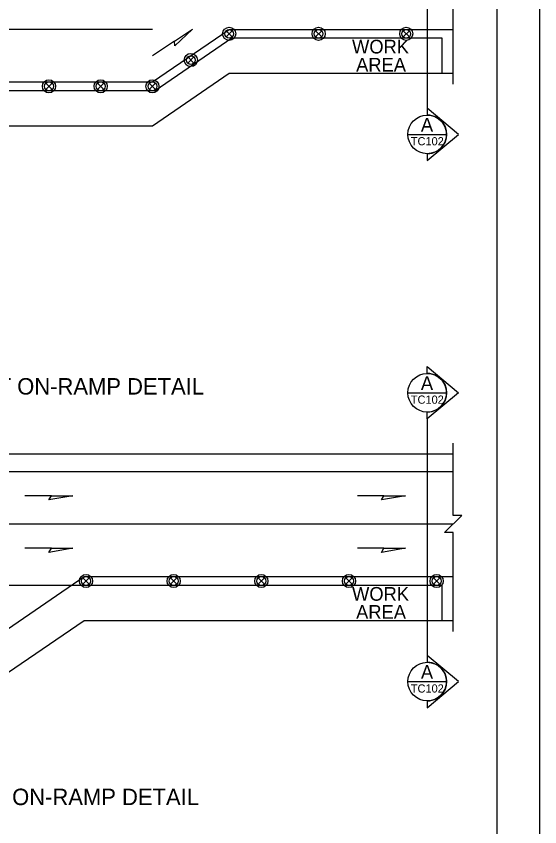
# Model space of a CAD drawing. Extents: x 99999.1 to 100055.7, y 99995 to 100013.2.
# Drawn here: x 100032.24 to 100036.06, y 100001.64 to 100007.56 of the extents above; entities that cross this region are included whole.
import ezdxf

# ---------------------------------------------------------------- set-up
doc = ezdxf.new("R2010")
doc.units = 0
for name, color, linetype in [('RD_MK_LineEdgeYellow', 7, 'Continuous'), ('RD_MK_LineLane', 7, 'Continuous'), ('SH_DE_DetailHeading2Text', 7, 'Continuous'), ('SH_GI_PlotLimits', 7, 'Continuous'), ('SH_GI_SheetBorder', 7, 'Continuous'), ('SH_TI_WZSectionCut', 7, 'Continuous'), ('TR_WZ_TrafficSafetyDrum', 7, 'Continuous'), ('TR_WZ_WorkAreaLabel', 7, 'Continuous'), ('TR_WZ_WorkZoneDetails', 7, 'Continuous')]:
    doc.layers.add(name, color=color, linetype=linetype)

msp = doc.modelspace()

# ---------------------------------------------------------------- linework, layer by layer
at = {"layer": 'RD_MK_LineEdgeYellow'}
for p, q in [((100033.2341, 100007.084), (100033.7951, 100007.468)), ((100033.7951, 100007.468), (100035.43, 100007.468)), ((100031.7238, 100007.084), (100033.2341, 100007.084)), ((100028.195, 100004.238), (100035.43, 100004.238)), ((100032.1758, 100003.086), (100032.7368, 100003.47)), ((100032.7368, 100003.47), (100035.43, 100003.47))]:
    msp.add_line(p, q, dxfattribs=at)
at = {"layer": 'RD_MK_LineLane'}
for points in [[(100033.2341, 100007.468), (100031.6607, 100007.468)], [(100035.43, 100003.854), (100028.195, 100003.854)]]:
    msp.add_lwpolyline(points, dxfattribs=at)
at = {"layer": 'SH_GI_PlotLimits'}
msp.add_lwpolyline([(100019.0625, 99999.6875), (100036.0625, 99999.6875), (100036.0625, 100010.6875), (100019.0625, 100010.6875)], close=True, dxfattribs=at)
at = {"layer": 'SH_GI_SheetBorder'}
msp.add_line((100035.75, 100010.375), (100035.75, 100000), dxfattribs=at)
at = {"layer": 'SH_TI_WZSectionCut'}
for p, q in [((100035.2407, 100008.62), (100035.2407, 100006.892)), ((100035.2407, 100006.892), (100035.2407, 100006.8421)), ((100035.4689, 100006.7009), (100035.2407, 100006.892)), ((100035.2407, 100006.5097), (100035.4689, 100006.7009)), ((100035.2407, 100006.5596), (100035.2407, 100006.5097)), ((100035.2407, 100004.9543), (100035.2407, 100005.0042)), ((100035.2407, 100005.0042), (100035.4688, 100004.8131)), ((100035.4688, 100004.8131), (100035.2407, 100004.622)), ((100035.2407, 100004.622), (100035.2407, 100004.6719)), ((100035.2407, 100004.622), (100035.2407, 100002.894)), ((100035.2407, 100002.894), (100035.2407, 100002.844)), ((100035.4689, 100002.7028), (100035.2407, 100002.894)), ((100035.2407, 100002.5117), (100035.4689, 100002.7028)), ((100035.2407, 100002.5616), (100035.2407, 100002.5117))]:
    msp.add_line(p, q, dxfattribs=at)
for points in [[(100035.0995, 100006.7009), (100035.3819, 100006.7009)], [(100035.0995, 100004.8131), (100035.3819, 100004.8131)], [(100035.0995, 100002.7028), (100035.3819, 100002.7028)]]:
    msp.add_lwpolyline(points, dxfattribs=at)
for centre in [(100035.2407, 100006.7009), (100035.2407, 100004.8131), (100035.2407, 100002.7028)]:
    msp.add_circle(centre, 0.1412, dxfattribs=at)
for centre in [(100035.2407, 100006.7009), (100035.2407, 100004.8131), (100035.2407, 100002.7028)]:
    msp.add_arc(centre, 0.1412, 269.99779, 90.00221, dxfattribs=at)
at = {"layer": 'TR_WZ_TrafficSafetyDrum'}
for p, q in [((100033.7725, 100007.4586), (100033.8177, 100007.4134)), ((100033.8177, 100007.4586), (100033.7725, 100007.4134)), ((100034.4251, 100007.4586), (100034.4703, 100007.4134)), ((100034.4703, 100007.4586), (100034.4251, 100007.4134)), ((100035.0651, 100007.4586), (100035.1103, 100007.4134)), ((100035.1103, 100007.4586), (100035.0651, 100007.4134)), ((100033.492, 100007.2666), (100033.5372, 100007.2214)), ((100033.5372, 100007.2666), (100033.492, 100007.2214)), ((100032.4563, 100007.0746), (100032.5016, 100007.0294)), ((100032.5016, 100007.0746), (100032.4563, 100007.0294)), ((100032.8339, 100007.0746), (100032.8791, 100007.0294)), ((100032.8791, 100007.0746), (100032.8339, 100007.0294)), ((100033.2115, 100007.0746), (100033.2567, 100007.0294)), ((100033.2567, 100007.0746), (100033.2115, 100007.0294)), ((100032.7268, 100003.4606), (100032.772, 100003.4153)), ((100032.772, 100003.4606), (100032.7268, 100003.4153)), ((100033.3668, 100003.4606), (100033.412, 100003.4153)), ((100033.412, 100003.4606), (100033.3668, 100003.4153)), ((100034.0068, 100003.4606), (100034.052, 100003.4153)), ((100034.052, 100003.4606), (100034.0068, 100003.4153)), ((100034.6468, 100003.4606), (100034.692, 100003.4153)), ((100034.692, 100003.4606), (100034.6468, 100003.4153)), ((100035.2868, 100003.4606), (100035.332, 100003.4153)), ((100035.332, 100003.4606), (100035.2868, 100003.4153))]:
    msp.add_line(p, q, dxfattribs=at)
for centre, radius in [((100033.7951, 100007.436), 0.048), ((100033.7951, 100007.436), 0.048), ((100033.7951, 100007.436), 0.032), ((100034.4477, 100007.436), 0.048), ((100034.4477, 100007.436), 0.048), ((100034.4477, 100007.436), 0.032), ((100035.0877, 100007.436), 0.048), ((100035.0877, 100007.436), 0.048), ((100035.0877, 100007.436), 0.032), ((100033.5146, 100007.244), 0.048), ((100033.5146, 100007.244), 0.048), ((100033.5146, 100007.244), 0.032), ((100032.4789, 100007.052), 0.048), ((100032.4789, 100007.052), 0.048), ((100032.4789, 100007.052), 0.032), ((100032.8565, 100007.052), 0.048), ((100032.8565, 100007.052), 0.048), ((100032.8565, 100007.052), 0.032), ((100033.2341, 100007.052), 0.048), ((100033.2341, 100007.052), 0.048), ((100033.2341, 100007.052), 0.032), ((100032.7494, 100003.438), 0.048), ((100032.7494, 100003.438), 0.048), ((100032.7494, 100003.438), 0.032), ((100033.3894, 100003.438), 0.048), ((100033.3894, 100003.438), 0.048), ((100033.3894, 100003.438), 0.032), ((100034.0294, 100003.438), 0.048), ((100034.0294, 100003.438), 0.048), ((100034.0294, 100003.438), 0.032), ((100034.6694, 100003.438), 0.048), ((100034.6694, 100003.438), 0.048), ((100034.6694, 100003.438), 0.032), ((100035.3094, 100003.438), 0.048), ((100035.3094, 100003.438), 0.048), ((100035.3094, 100003.438), 0.032)]:
    msp.add_circle(centre, radius, dxfattribs=at)
at = {"layer": 'TR_WZ_WorkZoneDetails'}
for p, q in [((100033.3951, 100007.3822), (100033.2341, 100007.276)), ((100033.2341, 100006.764), (100033.7951, 100007.148)), ((100033.7951, 100007.148), (100035.43, 100007.148)), ((100031.7105, 100006.764), (100033.2341, 100006.764)), ((100028.195, 100004.366), (100035.43, 100004.366)), ((100032.4968, 100004.0614), (100032.3039, 100004.0614)), ((100034.9242, 100004.0614), (100034.7313, 100004.0614)), ((100032.4968, 100003.6774), (100032.3039, 100003.6774)), ((100034.9242, 100003.6774), (100034.7313, 100003.6774)), ((100032.1758, 100002.766), (100032.7368, 100003.15)), ((100032.7368, 100003.15), (100035.43, 100003.15))]:
    msp.add_line(p, q, dxfattribs=at)
for points in [[(100035.43, 100007.068), (100035.43, 100007.7901), (100035.366, 100007.7901), (100035.494, 100007.9139), (100035.43, 100007.9139), (100035.43, 100008.444)], [(100035.43, 100003.07), (100035.43, 100003.792), (100035.366, 100003.792), (100035.494, 100003.9159), (100035.43, 100003.9159), (100035.43, 100004.446)]]:
    msp.add_lwpolyline(points, dxfattribs=at)
for points in [[(100033.5263, 100007.4688), (100033.3972, 100007.3467), (100033.3951, 100007.3822)], [(100033.8149, 100007.404), (100033.2539, 100007.02), (100031.7335, 100007.02), (100031.0462, 100006.7879), (100031.0462, 100006.7879), (100031.0462, 100006.7879), (100031.1223, 100006.564), (100031.1223, 100006.564), (100031.1223, 100006.564), (100031.7105, 100006.764), (100033.2341, 100006.764), (100033.5146, 100006.956), (100033.7951, 100007.148), (100035.35, 100007.148), (100035.35, 100007.404)], [(100032.654, 100004.0614), (100032.4789, 100004.0305), (100032.4968, 100004.0614)], [(100035.0815, 100004.0614), (100034.9064, 100004.0305), (100034.9242, 100004.0614)], [(100032.654, 100003.6774), (100032.4789, 100003.6465), (100032.4968, 100003.6774)], [(100035.0815, 100003.6774), (100034.9064, 100003.6465), (100034.9242, 100003.6774)], [(100028.275, 100003.406), (100028.275, 100003.15), (100029.2533, 100003.15), (100028.275, 100002.8199), (100028.275, 100002.8199), (100028.275, 100002.8199), (100028.275, 100001.9552), (100028.275, 100001.9552), (100028.275, 100001.9552), (100029.3341, 100002.3152), (100030.6601, 100002.766), (100032.1758, 100002.766), (100032.7368, 100003.15), (100035.35, 100003.15), (100035.35, 100003.406)]]:
    msp.add_lwpolyline(points, close=True, dxfattribs=at)

# ---------------------------------------------------------------- texts
at = {"layer": 'SH_DE_DetailHeading2Text'}
for s, p in [('OPEN RIGHT ON-RAMP DETAIL', (100031.2039, 100004.8003)), ('CLOSED RIGHT ON-RAMP DETAIL', (100030.9618, 100001.8009))]:
    msp.add_text(s, height=0.12, rotation=360, dxfattribs=at).set_placement(p)
at = {"layer": 'SH_TI_WZSectionCut'}
for s, height, rotation, p in [('A', 0.1, 0.00995, (100035.1945, 100006.7215)), ('TC102', 0.06, 360, (100035.1209, 100006.6209)), ('A', 0.1, 0.00995, (100035.1945, 100004.8337)), ('TC102', 0.06, 360, (100035.1209, 100004.7331)), ('A', 0.1, 0.00995, (100035.1945, 100002.7234)), ('TC102', 0.06, 360, (100035.1209, 100002.6228))]:
    msp.add_text(s, height=height, rotation=rotation, dxfattribs=at).set_placement(p)
at = {"layer": 'TR_WZ_WorkAreaLabel'}
for s, p in [('WORK', (100034.6919, 100007.292)), ('AREA', (100034.7215, 100007.16)), ('WORK', (100034.6919, 100003.294)), ('AREA', (100034.7215, 100003.1619))]:
    msp.add_text(s, height=0.1, dxfattribs=at).set_placement(p)

doc.saveas('drawing.dxf')
